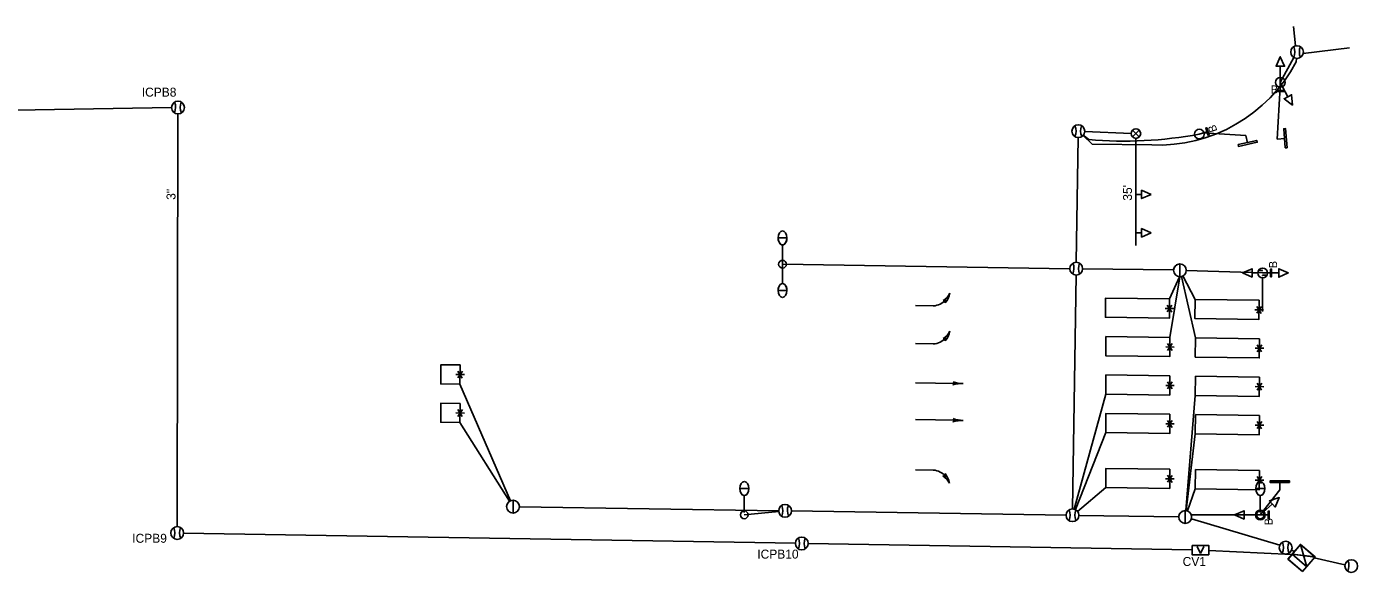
# Model space of a CAD drawing. Extents: x 596176 to 605330, y 332416 to 402398.
# Drawn here: x 604596.7 to 605010.6, y 349835.5 to 350006 of the extents above; entities that cross this region are included whole.
import ezdxf

# ---------------------------------------------------------------- set-up
doc = ezdxf.new("R2010")
doc.units = 0
for name, color, linetype in [('P_LTG', 7, 'Continuous'), ('P_SIG', 7, 'Continuous'), ('P_SIG_Bold', 7, 'Continuous'), ('P_SIG_Conduit', 7, 'Continuous'), ('P_SIG_IC', 7, 'Continuous'), ('P_SIG_Loops', 7, 'Continuous')]:
    doc.layers.add(name, color=color, linetype=linetype)

# ---------------------------------------------------------------- blocks, each defined once
blk = doc.blocks.new('CONTROL CABINET_4')
at = {"layer": 'P_SIG'}
for p, q in [((-0.114, 0.076), (0.114, 0.076)), ((-0.114, 0.076), (0.114, -0.076)), ((0.114, 0.076), (-0.114, -0.076))]:
    blk.add_line(p, q, dxfattribs=at)
blk.add_lwpolyline([(-0.114, 0.152), (0.114, 0.152), (0.114, -0.076), (-0.114, -0.076)], close=True, dxfattribs=at)
blk = doc.blocks.new('_U212')
at = {"layer": 'P_SIG'}
blk.add_circle((0, 0), 6.1, dxfattribs=at)
for centre, start, end in [((-15.5, 0.1), 336.6741, 22.5272), ((15.5, 0.1), 157.5751, 203.4282)]:
    blk.add_arc(centre, 13.3, start, end, dxfattribs=at)
blk = doc.blocks.new('COMMUNICATION VAULT_1')
at = {"layer": 'P_SIG'}
for p in [(-0.04, 0.041), (0.039, 0.041)]:
    blk.add_line(p, (-0.001, -0.041), dxfattribs=at)
blk.add_lwpolyline([(-0.099, 0.055), (0.099, 0.055), (0.099, -0.055), (-0.099, -0.055)], close=True, dxfattribs=at)
blk = doc.blocks.new('_U247')
at = {"layer": 'P_SIG_Bold'}
for p, q in [((-3, 0), (-0.1, 0)), ((-0.1, 0.1), (0.1, -0.1)), ((0.1, 0.1), (-0.1, -0.1))]:
    blk.add_line(p, q, dxfattribs=at)
blk.add_circle((0, 0), 0.114, dxfattribs=at)
blk.add_text("40'", height=0.213, dxfattribs=at).set_placement((-1.8, 0.1))
blk = doc.blocks.new('_U343')
at = {"layer": 'P_LTG'}
for p, q in [((4.3, 25), (-4.2, 25)), ((0, 0), (0, 18.5)), ((0, 0), (0, -18.3)), ((-4.3, -25), (4.2, -25))]:
    blk.add_line(p, q, dxfattribs=at)
blk.add_circle((0, 0), 3.68, dxfattribs=at)
for centre, major_axis in [((0, 25), (0, 6.65)), ((0, -25), (0, -6.65))]:
    blk.add_ellipse(centre, major_axis=major_axis, ratio=0.636439, dxfattribs=at)
for centre, major_axis in [((0, 25), (0, 6.65)), ((0, -25), (0, -6.65))]:
    blk.add_ellipse(centre, major_axis=major_axis, ratio=0.636439, start_param=1.570796, end_param=4.712389, dxfattribs=at)
blk = doc.blocks.new('_U344')
at = {"layer": 'P_LTG'}
for p, q in [((4.3, 25.1), (-4.1, 25.1)), ((0, 2.3), (0, 18.4))]:
    blk.add_line(p, q, dxfattribs=at)
blk.add_circle((0, 0.1), 3.68, dxfattribs=at)
blk.add_ellipse((0.1, 25.1), major_axis=(0, 6.65), ratio=0.636439, dxfattribs=at)
blk.add_ellipse((0.1, 25.1), major_axis=(0, 6.65), ratio=0.636439, start_param=1.570796, end_param=4.712389, dxfattribs=at)

msp = doc.modelspace()

# ---------------------------------------------------------------- linework, layer by layer
at = {"layer": 'P_SIG'}
for p, q in [((604988.34, 349993.64), (604988.33, 349988.58)), ((604988.34, 349993.64), (604988.33, 349988.58)), ((604988.33, 349988.58), (604988.31, 349986.08)), ((604990.7, 349984.11), (604988.33, 349988.58)), ((604987.37, 349970.89), (604988.31, 349987.06)), ((604963.03, 349972.42), (604965.41, 349973.18)), ((604977.53, 349972.03), (604964.22, 349972.8)), ((604977.53, 349972.03), (604978.05, 349969.69)), ((604987.37, 349970.89), (604989.77, 349971.09)), ((604945, 349953.6), (604943.23, 349953.6)), ((604945, 349941.59), (604943.23, 349941.59)), ((604956.99, 349931.89), (604956.97, 349927.89)), ((604979.53, 349929.08), (604981.3, 349929.08)), ((604987.86, 349929.06), (604982.8, 349929.08)), ((604984.3, 349929.08), (604985.3, 349929.08)), ((604874.33, 349918.89), (604879.92, 349918.79)), ((604883, 349920.5), (604883.89, 349920.66)), ((604883.63, 349919.73), (604883.89, 349920.66)), ((604883, 349908.62), (604883.89, 349908.79)), ((604883.63, 349907.85), (604883.89, 349908.79)), ((604874.33, 349907.02), (604879.92, 349906.92)), ((604874.33, 349894.8), (604886.9, 349894.57)), ((604874.33, 349883.28), (604886.9, 349883.05)), ((604874.33, 349867.61), (604879.92, 349867.51)), ((604882.93, 349865.69), (604883.82, 349865.5)), ((604883.6, 349866.44), (604883.82, 349865.5)), ((604988.24, 349861.34), (604988.24, 349863.74)), ((604988.24, 349861.34), (604982.08, 349853.5)), ((604748.67, 349858.09), (604748.65, 349854.09)), ((604985.82, 349856.9), (604982.08, 349853.5)), ((604958.65, 349854.86), (604958.63, 349850.86)), ((604977.02, 349853.51), (604982.08, 349853.5)), ((604977.02, 349853.51), (604982.08, 349853.5)), ((604982.08, 349853.5), (604984.58, 349853.5)), ((604996.6, 349837.33), (604994.64, 349844.27)), ((604996.6, 349837.33), (604992.04, 349841.23)), ((604992.04, 349841.23), (604999.2, 349840.37))]:
    msp.add_line(p, q, dxfattribs=at)
for points in [[(604988.34, 349996.6), (604989.66, 349993.64), (604987.02, 349993.64), (604988.34, 349996.6)], [(604988.34, 349996.6), (604989.66, 349993.64), (604987.02, 349993.64), (604988.34, 349996.6)], [(604989.66, 349993.64), (604988.34, 349996.6), (604987.02, 349993.64), (604989.66, 349993.64)], [(604988.34, 349996.6), (604989.66, 349993.64), (604987.02, 349993.64), (604988.34, 349996.6)], [(604992.1, 349981.5), (604989.54, 349983.49), (604991.87, 349984.73), (604992.1, 349981.5)], [(604989.54, 349983.49), (604992.1, 349981.5), (604991.87, 349984.73), (604989.54, 349983.49)], [(604992.1, 349981.5), (604989.54, 349983.49), (604991.87, 349984.73), (604992.1, 349981.5)], [(604956.97, 349927.89), (604956.99, 349931.89)], [(604990.82, 349929.06), (604987.86, 349927.75), (604987.86, 349930.38), (604990.82, 349929.06)], [(604987.86, 349927.75), (604990.82, 349929.06), (604987.86, 349930.38), (604987.86, 349927.75)], [(604990.82, 349929.06), (604987.86, 349927.75), (604987.86, 349930.38), (604990.82, 349929.06)], [(604886.09, 349894.09), (604886.9, 349894.57), (604886.11, 349895.09)], [(604886.09, 349882.57), (604886.9, 349883.05), (604886.11, 349883.57)], [(604748.65, 349854.09), (604748.67, 349858.09)], [(604988, 349858.9), (604986.71, 349855.93), (604984.93, 349857.87), (604988, 349858.9)], [(604986.71, 349855.93), (604988, 349858.9), (604984.93, 349857.87), (604986.71, 349855.93)], [(604988, 349858.9), (604986.71, 349855.93), (604984.93, 349857.87), (604988, 349858.9)], [(604958.63, 349850.86), (604958.65, 349854.86)], [(604974.06, 349853.51), (604977.02, 349854.83), (604977.02, 349852.19), (604974.06, 349853.51)], [(604974.06, 349853.51), (604977.02, 349854.83), (604977.02, 349852.19), (604974.06, 349853.51)], [(604977.02, 349854.83), (604974.06, 349853.51), (604977.02, 349852.19), (604977.02, 349854.83)], [(604974.06, 349853.51), (604977.02, 349854.83), (604977.02, 349852.19), (604974.06, 349853.51)]]:
    msp.add_lwpolyline(points, dxfattribs=at)
for points in [[(604987.11, 349986.09), (604989.51, 349986.07), (604989.5, 349985.74), (604987.1, 349985.77)], [(604965.78, 349972.04), (604965.05, 349974.32), (604965.36, 349974.42), (604966.09, 349972.14)], [(604989.87, 349968.13), (604989.39, 349974.11), (604989.98, 349974.16), (604990.47, 349968.17)], [(604975.14, 349969.18), (604980.99, 349970.48), (604981.12, 349969.89), (604975.27, 349968.59)], [(604947.95, 349953.6), (604945, 349952.28), (604945, 349954.91)], [(604947.95, 349941.59), (604945, 349940.27), (604945, 349942.91)], [(604976.57, 349929.08), (604979.53, 349930.4), (604979.53, 349927.76)], [(604985.3, 349927.88), (604985.3, 349930.28), (604985.63, 349930.28), (604985.63, 349927.88)], [(604991.2, 349863.6), (604985.2, 349863.6), (604985.2, 349864.2), (604991.2, 349864.2)], [(604984.58, 349852.3), (604984.58, 349854.7), (604984.91, 349854.7), (604984.91, 349852.3)], [(604995.3, 349835.81), (604990.74, 349839.71), (604994.64, 349844.27), (604999.2, 349840.37)]]:
    msp.add_lwpolyline(points, close=True, dxfattribs=at)
for centre, radius in [((604993.58, 349998.04), 2), ((604988.33, 349988.58), 1.52), ((604988.33, 349988.58), 1.52), ((604925.24, 349973.34), 2), ((604963.03, 349972.42), 1.52), ((604924.58, 349930.39), 2), ((604956.98, 349929.89), 2), ((604982.8, 349929.08), 1.52), ((604748.66, 349856.09), 2), ((604833.65, 349854.78), 2), ((604923.42, 349853.4), 2), ((604982.08, 349853.5), 1.52), ((604982.08, 349853.5), 1.52), ((604958.64, 349852.86), 2), ((604990.02, 349843.27), 2), ((605010.5, 349837.53), 2)]:
    msp.add_circle(centre, radius, dxfattribs=at)
for centre, radius, start, end in [((604988.51, 349998.07), 4.36, 336.6741, 22.5272), ((604998.65, 349998.08), 4.36, 157.5751, 203.4282), ((604988.33, 349988.58), 1.52, 90, 270), ((604988.33, 349988.58), 1.52, 270, 90), ((604920.17, 349973.38), 4.36, 336.6741, 22.5272), ((604930.31, 349973.39), 4.36, 157.5751, 203.4282), ((604963.03, 349972.42), 1.52, 0, 180), ((604963.03, 349972.42), 1.52, 180, 0), ((604919.51, 349930.43), 4.36, 336.6741, 22.5272), ((604929.65, 349930.44), 4.36, 157.5751, 203.4282), ((604956.98, 349929.89), 2, 89.7008, 180), ((604956.98, 349929.89), 2, 180, 269.7008), ((604982.8, 349929.08), 1.52, 0, 180), ((604982.8, 349929.08), 1.52, 180, 0), ((604880.5, 349924.99), 5.14, 299.0618, 333.7102), ((604879.14, 349923.8), 6.07, 317.8054, 349.6616), ((604879.62, 349924.58), 5.8, 272.9422, 317.5061), ((604879.62, 349912.71), 5.8, 272.9422, 317.5061), ((604880.5, 349913.12), 5.14, 299.0618, 333.7102), ((604879.14, 349911.93), 6.07, 317.8054, 349.6616), ((604889.11, 349884.04), 10.49, 88.9769, 106.7392), ((604889.48, 349905.02), 10.49, 251.2146, 268.9769), ((604889.11, 349872.52), 10.49, 88.9769, 106.7392), ((604889.48, 349893.5), 10.49, 251.2146, 268.9769), ((604879.41, 349861.74), 5.8, 40.4477, 85.0116), ((604880.28, 349861.29), 5.14, 24.2436, 58.892), ((604878.96, 349862.53), 6.07, 8.2922, 40.1484), ((604748.66, 349856.09), 2, 89.7008, 180), ((604748.66, 349856.09), 2, 180, 269.7008), ((604828.58, 349854.82), 4.36, 336.6741, 22.5272), ((604838.72, 349854.83), 4.36, 157.5751, 203.4282), ((604918.35, 349853.44), 4.36, 336.6741, 22.5272), ((604928.49, 349853.45), 4.36, 157.5751, 203.4282), ((604982.08, 349853.5), 1.52, 0, 180), ((604958.64, 349852.86), 2, 89.7008, 180), ((604958.64, 349852.86), 2, 180, 269.7008), ((604982.08, 349853.5), 1.52, 180, 0), ((604984.95, 349843.31), 4.36, 336.6741, 22.5272), ((604995.09, 349843.32), 4.36, 157.5751, 203.4282), ((605005.42, 349837.56), 4.36, 336.6741, 22.5272)]:
    msp.add_arc(centre, radius, start, end, dxfattribs=at)
at = {"layer": 'P_SIG_Bold'}
for p, q in [((604942.16, 349971.54), (604944.29, 349973.66)), ((604942.16, 349973.66), (604944.29, 349971.54)), ((604943.23, 349937.6), (604943.23, 349971.1)), ((604982.8, 349917.08), (604982.8, 349927.58))]:
    msp.add_line(p, q, dxfattribs=at)
msp.add_circle((604943.23, 349972.6), 1.5, dxfattribs=at)
at = {"layer": 'P_SIG_Conduit'}
for p, q in [((604992.45, 350006.03), (604993.06, 349999.97)), ((604992.57, 349996.31), (604988.33, 349988.58)), ((604995.53, 349997.61), (605009.95, 349999.36)), ((604924.61, 349932.39), (604925.21, 349971.34)), ((604922.58, 349930.4), (604832.84, 349931.8)), ((604926.58, 349930.36), (604954.98, 349930.01)), ((604958.98, 349929.83), (604982.8, 349929.08)), ((604923.45, 349855.4), (604924.57, 349928.39)), ((604831.65, 349854.81), (604750.66, 349856.06)), ((604831.66, 349854.58), (604820.87, 349853.5)), ((604921.42, 349853.43), (604835.65, 349854.75)), ((604956.64, 349852.89), (604925.42, 349853.37)), ((604960.53, 349853.5), (604982.08, 349853.5)), ((604988.19, 349844.08), (604960.55, 349852.29)), ((604992.76, 349842.07), (604991.85, 349842.47))]:
    msp.add_line(p, q, dxfattribs=at)
for points in [[(604993.3, 349994.95), (604993.4, 349996.05)], [(604926.71, 349971.99), (604929.61, 349969.32), (604948.17, 349969.03)], [(604926.8, 349972.08), (604928.49, 349970.72)], [(604927.24, 349973.26), (604941.73, 349972.66)], [(605008.54, 349837.96), (604998.94, 349840.07)]]:
    msp.add_lwpolyline(points, dxfattribs=at)
for centre, radius, start, end in [((604950.15, 350017.85), 48.85, 267.682, 332.0466), ((604939.54, 350098.42), 128.17, 265.0539, 280.5633)]:
    msp.add_arc(centre, radius, start, end, dxfattribs=at)
at = {"layer": 'P_SIG_IC'}
for points in [[(604508.1, 349986.64), (604517.18, 349985.97), (604574.92, 349979.61), (604641.97, 349980.69)], [(604643.97, 349978.73), (604643.76, 349849.88)], [(604645.75, 349847.85), (604836.86, 349844.64)], [(604840.86, 349844.57), (604960.78, 349842.56)], [(604966, 349842.38), (604991.92, 349841.1)]]:
    msp.add_lwpolyline(points, dxfattribs=at)
at = {"layer": 'P_SIG_Loops'}
for p, q in [((604956.81, 349927.9), (604953.77, 349920.94)), ((604956.91, 349927.9), (604953.87, 349908.94)), ((604961.87, 349908.82), (604957.43, 349927.95)), ((604961.77, 349920.82), (604957.91, 349928.13)), ((604955.1, 349917.94), (604952.42, 349917.98)), ((604953.01, 349919.04), (604954.41, 349916.85)), ((604954.46, 349919.03), (604953.03, 349916.88)), ((604953.73, 349917.94), (604953.77, 349920.94)), ((604983.1, 349917.54), (604980.42, 349917.58)), ((604981.01, 349918.64), (604982.41, 349916.45)), ((604982.46, 349918.63), (604981.02, 349916.48)), ((604981.73, 349917.54), (604981.77, 349920.54)), ((604953.83, 349905.94), (604953.87, 349908.94)), ((604955.2, 349905.93), (604952.53, 349905.97)), ((604953.11, 349907.04), (604954.51, 349904.85)), ((604954.57, 349907.03), (604953.13, 349904.88)), ((604983.2, 349905.53), (604980.52, 349905.57)), ((604981.11, 349906.64), (604982.51, 349904.45)), ((604982.56, 349906.63), (604981.12, 349904.48)), ((604981.83, 349905.54), (604981.87, 349908.53)), ((604733.48, 349897.33), (604730.8, 349897.37)), ((604731.39, 349898.43), (604732.79, 349896.24)), ((604732.84, 349898.43), (604731.4, 349896.27)), ((604732.11, 349897.33), (604732.15, 349900.33)), ((604953.83, 349893.93), (604953.87, 349896.93)), ((604981.83, 349893.53), (604981.87, 349896.53)), ((604732.06, 349894.33), (604747.86, 349857.92)), ((604955.2, 349893.93), (604952.53, 349893.97)), ((604953.11, 349895.04), (604954.51, 349892.84)), ((604954.57, 349895.03), (604953.13, 349892.87)), ((604983.2, 349893.53), (604980.52, 349893.57)), ((604981.11, 349894.64), (604982.51, 349892.44)), ((604982.56, 349894.63), (604981.12, 349892.47)), ((604732.11, 349885.33), (604732.15, 349888.33)), ((604923.95, 349855.33), (604933.79, 349891.22)), ((604961.79, 349890.82), (604958.8, 349854.85)), ((604733.48, 349885.33), (604730.8, 349885.37)), ((604731.39, 349886.44), (604732.79, 349884.24)), ((604732.84, 349886.43), (604731.4, 349884.27)), ((604953.83, 349881.93), (604953.87, 349884.93)), ((604981.83, 349881.53), (604981.87, 349884.53)), ((604747.59, 349857.78), (604732.06, 349882.33)), ((604955.2, 349881.93), (604952.53, 349881.97)), ((604953.11, 349883.04), (604954.51, 349880.84)), ((604954.57, 349883.03), (604953.13, 349880.88)), ((604983.2, 349881.53), (604980.52, 349881.57)), ((604981.11, 349882.64), (604982.51, 349880.44)), ((604982.56, 349882.63), (604981.12, 349880.48)), ((604924.31, 349855.19), (604933.79, 349879.22)), ((604958.88, 349854.84), (604961.79, 349878.82)), ((604953.83, 349864.76), (604953.87, 349867.76)), ((604981.83, 349864.36), (604981.87, 349867.36)), ((604955.2, 349864.76), (604952.52, 349864.8)), ((604953.11, 349865.87), (604954.51, 349863.67)), ((604954.57, 349865.86), (604953.13, 349863.71)), ((604983.2, 349864.36), (604980.52, 349864.4)), ((604981.11, 349865.47), (604982.51, 349863.27)), ((604982.56, 349865.46), (604981.12, 349863.3)), ((604925.03, 349854.58), (604933.79, 349862.05)), ((604959.31, 349854.74), (604961.79, 349861.65))]:
    msp.add_line(p, q, dxfattribs=at)
for points in [[(604953.77, 349920.94), (604933.77, 349921.23), (604933.69, 349915.23), (604953.69, 349914.94)], [(604981.77, 349920.54), (604961.77, 349920.82), (604961.68, 349914.83), (604981.68, 349914.54)], [(604953.87, 349908.94), (604933.87, 349909.22), (604933.79, 349903.22), (604953.79, 349902.94)], [(604981.87, 349908.53), (604961.87, 349908.82), (604961.79, 349902.82), (604981.78, 349902.54)], [(604732.15, 349900.33), (604726.15, 349900.42), (604726.06, 349894.42), (604732.06, 349894.33)], [(604953.87, 349896.93), (604933.87, 349897.22), (604933.79, 349891.22), (604953.79, 349890.93)], [(604981.87, 349896.53), (604961.87, 349896.82), (604961.79, 349890.82), (604981.78, 349890.53)], [(604732.15, 349888.33), (604726.15, 349888.42), (604726.06, 349882.42), (604732.06, 349882.33)], [(604953.87, 349884.93), (604933.87, 349885.22), (604933.79, 349879.22), (604953.79, 349878.93)], [(604981.87, 349884.53), (604961.87, 349884.82), (604961.79, 349878.82), (604981.78, 349878.53)], [(604953.87, 349867.76), (604933.87, 349868.05), (604933.79, 349862.05), (604953.79, 349861.76)], [(604981.87, 349867.36), (604961.87, 349867.65), (604961.79, 349861.65), (604981.78, 349861.36)]]:
    msp.add_lwpolyline(points, close=True, dxfattribs=at)

# ---------------------------------------------------------------- block references
at = {"layer": 'P_LTG', "xscale": 0.32808333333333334, "yscale": 0.32808333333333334, "rotation": 180}
for name, p in [('_U343', (604832.84, 349931.8)), ('_U247', (604982.82, 349928.33))]:
    msp.add_blockref(name, p, dxfattribs=at)
at = {"layer": 'P_LTG', "xscale": 0.32808333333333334, "yscale": 0.32808333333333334}
for name, p in [('_U247', (604982.79, 349929.83)), ('_U344', (604820.88, 349853.5)), ('_U344', (604982.08, 349853.5))]:
    msp.add_blockref(name, p, dxfattribs=at)
at = {"layer": 'P_SIG', "xscale": 26.246666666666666, "yscale": 26.246666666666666, "rotation": 139.2265202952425}
msp.add_blockref('CONTROL CABINET_4', (604995.62, 349840.8), dxfattribs=at)
at = {"layer": 'P_SIG_IC'}
for name, p, xscale, yscale in [('_U212', (604643.98, 349980.72), 0.32808333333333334, 0.32808333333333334), ('_U212', (604643.76, 349847.88), 0.32808333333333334, 0.32808333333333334), ('_U212', (604838.86, 349844.6), 0.32808333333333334, 0.32808333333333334), ('COMMUNICATION VAULT_1', (604963.39, 349842.53), 26.246666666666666, 26.246666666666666)]:
    msp.add_blockref(name, p, dxfattribs=dict(at, xscale=xscale, yscale=yscale))

# ---------------------------------------------------------------- texts
at = {"layer": 'P_SIG'}
for rotation, p in [(359.4326, (604985.38, 349985.1)), (107.7527, (604968.7, 349973.44)), (90.015, (604987.32, 349930.58)), (90.015, (604985.94, 349850.25))]:
    msp.add_text('B', height=2.52, rotation=rotation, dxfattribs=at).set_placement(p)
at = {"layer": 'P_SIG_Bold'}
msp.add_text("35'", height=2.8, rotation=90, dxfattribs=at).set_placement((604942.01, 349951.64))
at = {"layer": 'P_SIG_IC'}
for s, p in [('ICPB8', (604632.69, 349984.13)), ('ICPB9', (604629.71, 349844.81)), ('ICPB10', (604824.96, 349839.87)), ('CV1', (604957.83, 349837.56))]:
    msp.add_text(s, height=2.8, dxfattribs=at).set_placement(p)
msp.add_text('3"', height=2.8, rotation=89.9625, dxfattribs=at).set_placement((604643.22, 349951.9))

doc.saveas('drawing.dxf')
